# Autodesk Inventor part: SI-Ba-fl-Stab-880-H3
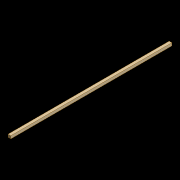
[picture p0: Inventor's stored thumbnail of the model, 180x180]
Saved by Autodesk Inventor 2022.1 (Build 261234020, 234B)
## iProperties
Part Number: SI-Ba-fl-Stab-880-H3
Material: Allgemein
Document SubType Name: Modellieren
Designer: joachim
Appearance: Vorgabe
Author: joachim
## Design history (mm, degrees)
sketch "Skizze1"
  geometry: L1 (0, 0)-(15, 0); L2 (15, 0)-(15, 15); L3 (15, 15)-(0, 15); L4 (0, 15)-(0, 0)
  constraints: 8 end point, 2 parallel, 1 horizontal, 1 perpendicular
  dimensions: "d0" = 15 distance of L3.end L2.end; "d1" = 15 distance of L2.end L1.end
extrude "Extrusion1" new body sketch "Skizze1" distance "d2" = 880; taper "d3" = 0 deg
node "Volumenkörper1"
node "Volumenkörper"
node "Flächenkörper"
